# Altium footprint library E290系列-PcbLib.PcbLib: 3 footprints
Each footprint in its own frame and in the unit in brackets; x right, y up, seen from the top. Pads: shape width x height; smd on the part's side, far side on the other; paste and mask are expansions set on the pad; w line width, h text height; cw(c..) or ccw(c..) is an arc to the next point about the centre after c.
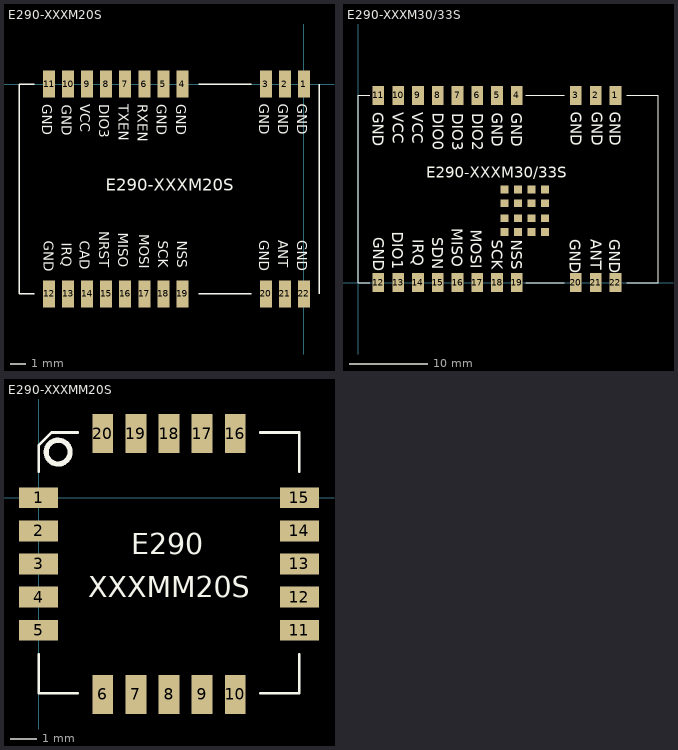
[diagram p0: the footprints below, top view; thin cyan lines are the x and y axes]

## E290-XXXM20S [mm] "20mm*14mm*2.8mm-S"
pads (22):
  rect 0.8x1.8 smd: 1(0,0) 2(-1.27,0) 3(-2.54,0) 4(-8.11,0) 5(-9.38,0) 6(-10.65,0) 7(-11.92,0) 8(-13.19,0) 9(-14.46,0) 10(-15.73,0) 11(-17,0) 12(-17,-14) 13(-15.73,-14) 14(-14.46,-14) 15(-13.19,-14) 16(-11.92,-14) 17(-10.65,-14) 18(-9.38,-14) 19(-8.11,-14) 20(-2.54,-14) 21(-1.27,-14) 22(0,-14)
Top Overlay:
  lines w0.1: -18,-14 -19,-14 -19,0 -18,0 ; -7,-14 -3.5,-14 ; -7,0 -3.5,0 ; 1,-14 1,0
  text "GND" at -8.528,-1.353 h0.65
  text "GND" at -9.807,-1.353 h0.65
  text "RXEN" at -11.086,-1.353 h0.65
  text "TXEN" at -12.364,-1.353 h0.65
  text "DIO3" at -13.643,-1.353 h0.65
  text "VCC" at -14.922,-1.353 h0.65
  text "GND" at -16.14,-1.373 h0.65
  text "GND" at -17.45,-1.353 h0.65
  text "GND" at -2.996,-1.323 h0.65
  text "GND" at -1.717,-1.323 h0.65
  text "GND" at -0.438,-1.323 h0.65
  text "GND" at -0.438,-10.428 h0.65
  text "ANT" at -1.717,-10.428 h0.65
  text "GND" at -2.996,-10.428 h0.65
  text "GND" at -17.349,-10.459 h0.65
  text "IRQ" at -16.14,-10.567 h0.65
  text "CAD" at -14.936,-10.459 h0.65
  text "NRST" at -13.666,-9.809 h0.65
  text "MISO" at -12.396,-9.917 h0.65
  text "MOSI" at -10.999,-10.026 h0.65
  text "SCK" at -9.729,-10.459 h0.65
  text "NSS" at -8.459,-10.459 h0.65
  text "E290-XXXM20S" at -13.208,-7.112 h0.8

## E290-XXXM30/33S [mm]
pads (38):
  rect 1.5x2.5 smd: 1(33.04,24) 2(30.5,24) 3(27.96,24) 4(20.39,24) 5(17.85,24) 6(15.31,24) 7(12.77,24) 8(10.23,24) 9(7.69,24) 10(5.15,24) 11(2.61,24) 12(2.61,0) 13(5.15,0) 14(7.69,0) 15(10.23,0) 16(12.77,0) 17(15.31,0) 18(17.85,0) 19(20.39,0) 20(27.96,0) 21(30.5,0) 22(33.04,0)
  rect 1x1 smd: 22(18.796,6.477) 22(18.796,8.255) 22(18.796,10.16) 22(18.796,11.938) 22(20.532,6.477) 22(20.532,8.255) 22(20.532,10.16) 22(20.532,11.938) 22(22.267,6.477) 22(22.267,8.255) 22(22.267,10.16) 22(22.267,11.938) 22(24.003,6.477) 22(24.003,8.255) 22(24.003,10.16) 22(24.003,11.938)
Top Overlay:
  lines w0.1: 1.5,0 0,0 0,24 1.5,24 ; 21.5,0 26.5,0 ; 21.5,24 26.5,24 ; 34.5,0 38.5,0 38.5,24 34.5,24
  text "E290-XXXM30/33S" at 8.763,13.462 h1.4
  text "GND" at 19.674,21.777 h1.4
  text "GND" at 17.141,21.777 h1.4
  text "DIO2" at 14.638,21.704 h1.4
  text "DIO3" at 12.105,21.704 h1.4
  text "DIO0" at 9.602,21.756 h1.4
  text "VCC" at 6.964,21.822 h1.4
  text "VCC" at 4.43,21.822 h1.4
  text "GND" at 1.897,21.822 h1.4
  text "GND" at 27.297,21.882 h1.4
  text "GND" at 29.97,21.882 h1.4
  text "GND" at 32.292,21.882 h1.4
  text "GND" at 32.265,5.582 h1.4
  text "ANT" at 29.838,5.582 h1.4
  text "GND" at 27.196,5.582 h1.4
  text "GND" at 1.961,5.809 h1.4
  text "DIO1" at 4.381,6.509 h1.4
  text "IRQ" at 7.042,5.576 h1.4
  text "SDN" at 9.507,5.809 h1.4
  text "MISO" at 12.032,6.975 h1.4
  text "MOSI" at 14.497,6.742 h1.4
  text "SCK" at 17.145,5.461 h1.4
  text "NSS" at 19.685,5.461 h1.4

## E290-XXXMM20S [mm]
height 2.5
pads (20):
  rect 1.5x0.8 smd mask+0.102: 1(0,0) 2(0,-1.27) 3(0,-2.54) 4(0,-3.81) 5(0,-5.08) 11(10,-5.08) 12(10,-3.81) 13(10,-2.54) 14(10,-1.27) 15(10,0)
  rect 0.8x1.5 smd mask+0.102: 6(2.46,-7.54) 7(3.73,-7.54) 8(5,-7.54) 9(6.27,-7.54) 10(7.54,-7.54) 16(7.54,2.46) 17(6.27,2.46) 18(5,2.46) 19(3.73,2.46) 20(2.46,2.46)
Top Overlay:
  circle w0.2: c0.75,1.75 r0.458
  lines w0.1: 0,-6 0,-7.5 1.5,-7.5 ; 0,1 0,2 0.5,2.5 1.5,2.5 ; 8.5,-7.5 10,-7.5 10,-6 ; 8.5,2.5 10,2.5 10,1
  text "E290" at 3.556,-2.159 h0.8
  text "XXXMM20S" at 1.905,-3.81 h0.8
